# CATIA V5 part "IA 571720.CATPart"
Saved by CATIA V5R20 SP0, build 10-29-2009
Part number: IA 571720
Revision: ANY
Definition: UNKNOWN
Nomenclature: IA 571720
Source: Unknown
Bounding box of the stored display mesh (mm): x -2.85 to 2.85, y -7.925 to 9.045, z -2.711 to 2.711
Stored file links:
  C:\Users\Utente\Desktop\IO LAVORO\3D X SITO CF\CUMSA\3D files IA\IA 571720\IA 571720.CATPart
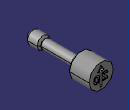
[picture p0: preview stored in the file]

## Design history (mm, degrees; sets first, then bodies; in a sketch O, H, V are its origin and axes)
Body1 "Cortar-Extruir4" (main body)
  Solid1: solid without history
